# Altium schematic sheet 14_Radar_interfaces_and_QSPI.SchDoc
size 289 x 396 mm
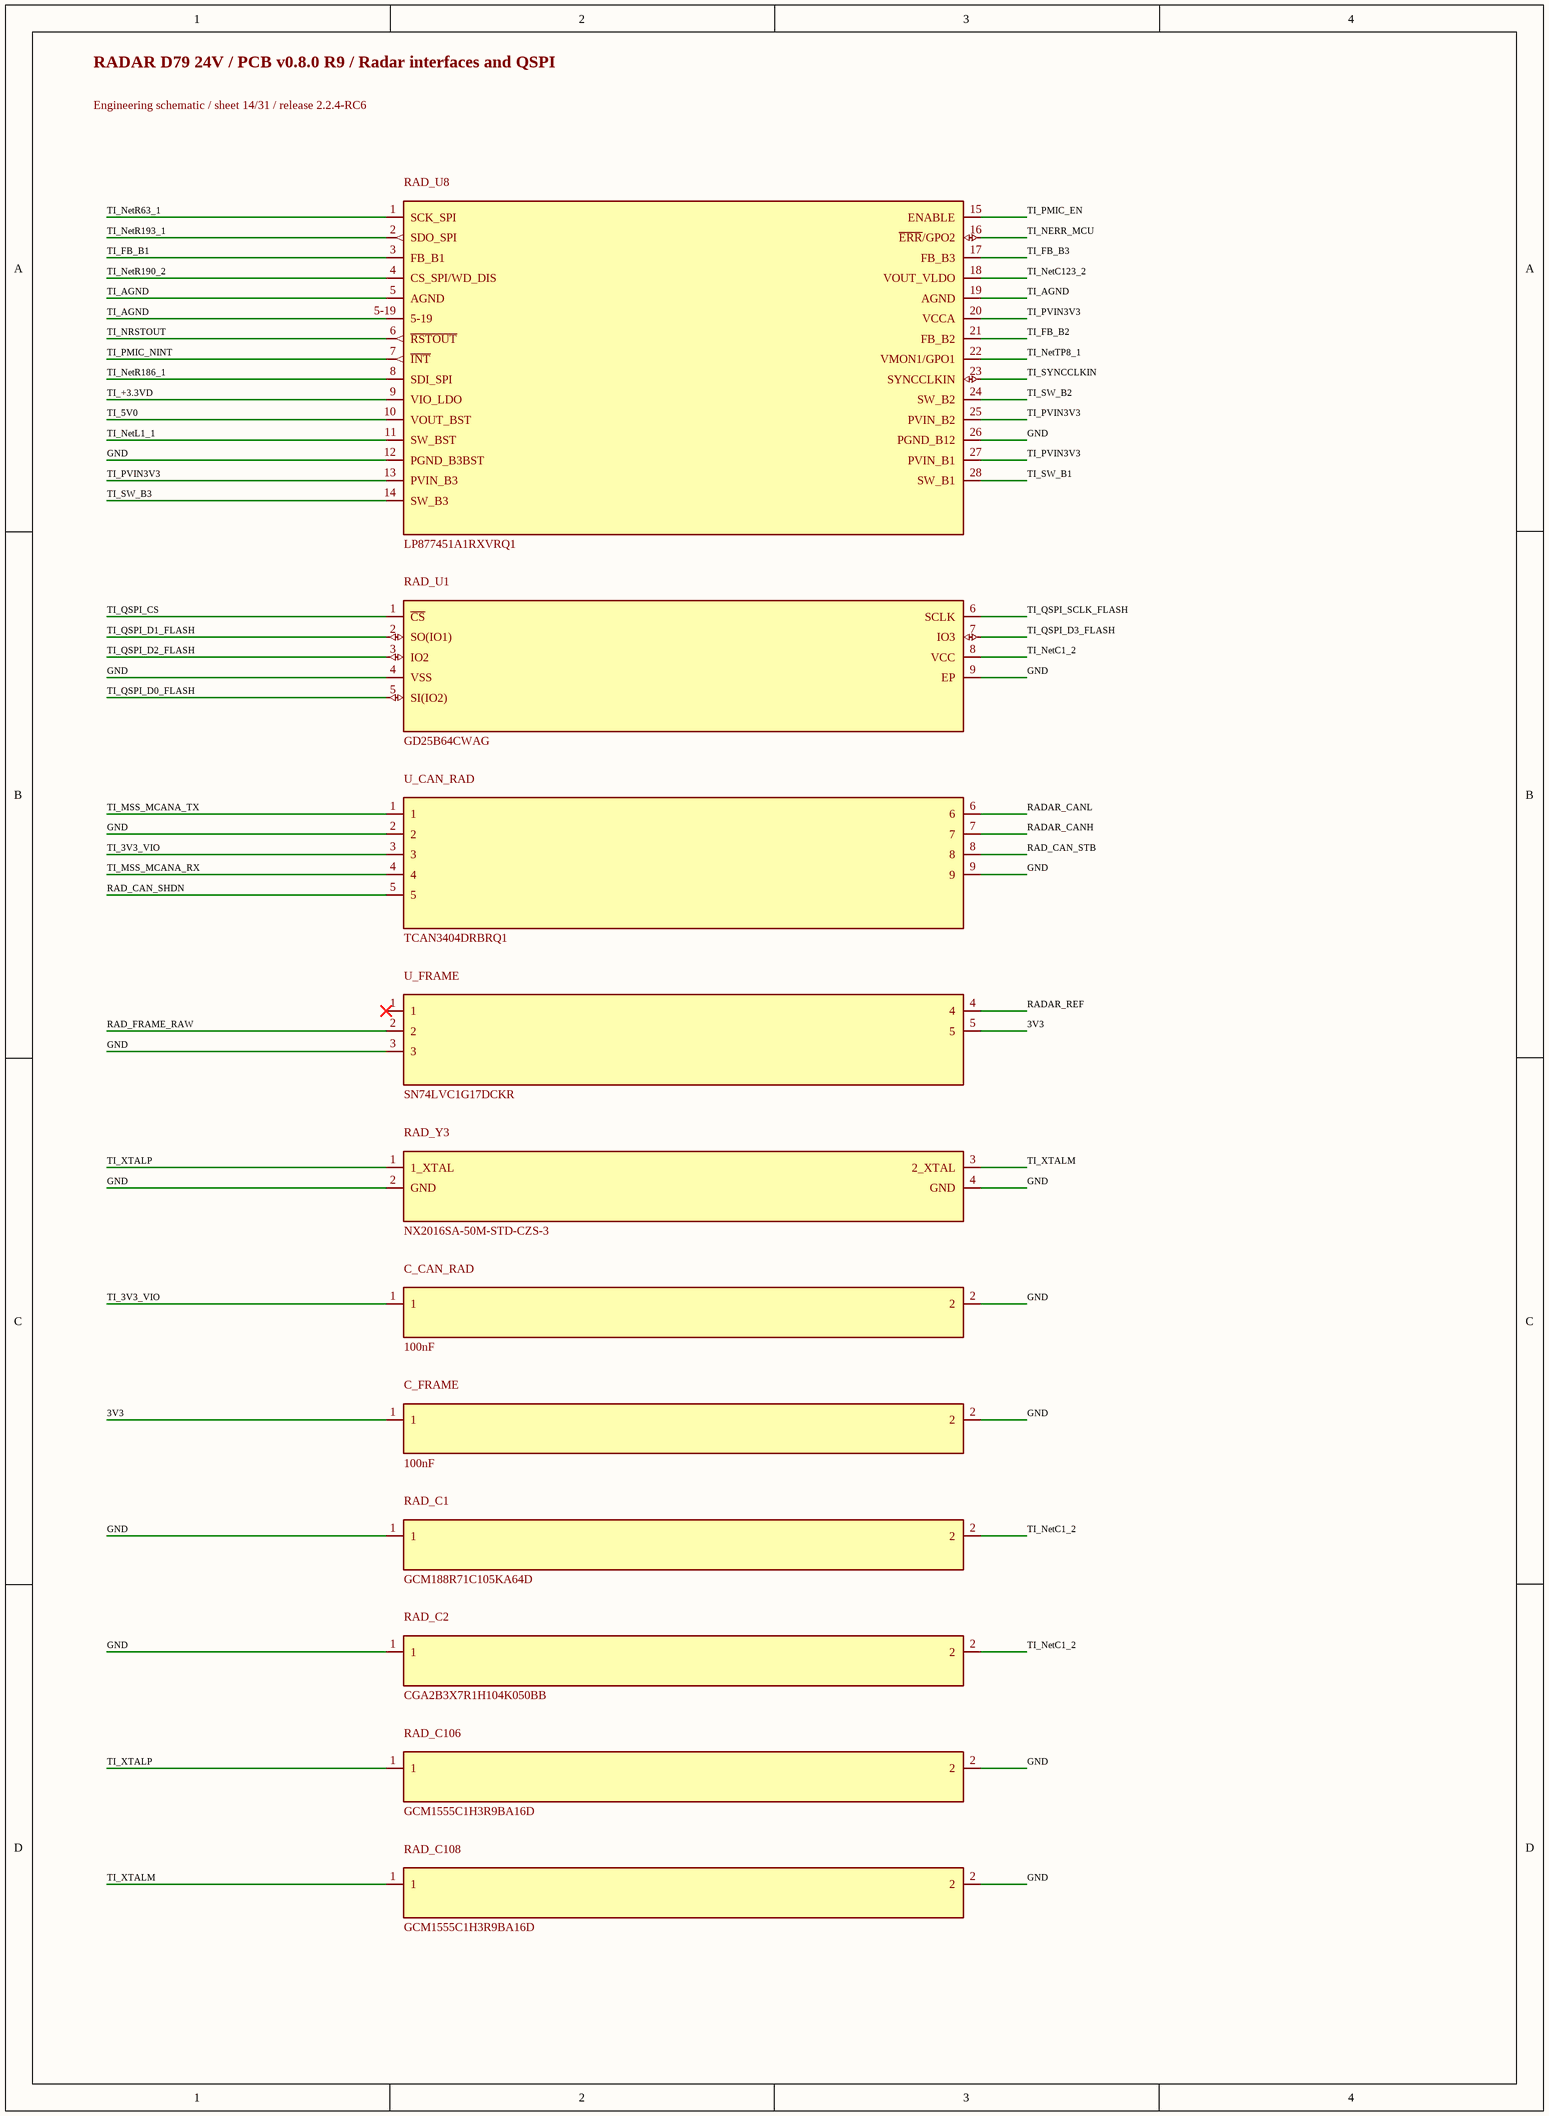
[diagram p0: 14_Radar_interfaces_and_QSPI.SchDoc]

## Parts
C_CAN_RAD  100nF  [C_0402_1005Metric]
C_FRAME  100nF  [C_0402_1005Metric]
RAD_C1  GCM188R71C105KA64D  [0603L]
RAD_C2  CGA2B3X7R1H104K050BB  [0402L]
RAD_C106  GCM1555C1H3R9BA16D  [FP-GCM1555C1H3R9BA16D_0402-MFG]
RAD_C108  GCM1555C1H3R9BA16D  [FP-GCM1555C1H3R9BA16D_0402-MFG]
RAD_U1  GD25B64CWAG  [FP-GD25B64CWAG_WSON8-IPC_C]
RAD_U8  LP877451A1RXVRQ1  [RXV0028A-MFG]
RAD_Y3  NX2016SA-50M-STD-CZS-3  [FP-NX2016SA-50M-STD-CZS-3_SMT4_2MM0_1MM6-MFG]
U_CAN_RAD  TCAN3404DRBRQ1  [Texas_DRB0008A]
U_FRAME  SN74LVC1G17DCKR  [DCK0005A_N]

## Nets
3V3: C_FRAME.1 U_FRAME.5
GND: C_CAN_RAD.2 C_FRAME.2 RAD_C1.1 RAD_C2.1 RAD_C106.2 RAD_C108.2 RAD_U1.4(VSS) RAD_U1.9(EP) RAD_U8.12(PGND_B3BST) RAD_U8.26(PGND_B12) RAD_Y3.2(GND) RAD_Y3.4(GND) U_CAN_RAD.2 U_CAN_RAD.9 U_FRAME.3
RAD_CAN_SHDN: U_CAN_RAD.5
RAD_CAN_STB: U_CAN_RAD.8
RAD_FRAME_RAW: U_FRAME.2
RADAR_CANH: U_CAN_RAD.7
RADAR_CANL: U_CAN_RAD.6
RADAR_REF: U_FRAME.4
TI_3V3_VIO: C_CAN_RAD.1 U_CAN_RAD.3
TI_5V0: RAD_U8.10(VOUT_BST)
TI_+3.3VD: RAD_U8.9(VIO_LDO)
TI_AGND: RAD_U8.5(AGND) RAD_U8.5-19 RAD_U8.19(AGND)
TI_FB_B1: RAD_U8.3(FB_B1)
TI_FB_B2: RAD_U8.21(FB_B2)
TI_FB_B3: RAD_U8.17(FB_B3)
TI_MSS_MCANA_RX: U_CAN_RAD.4
TI_MSS_MCANA_TX: U_CAN_RAD.1
TI_NERR_MCU: RAD_U8.16(~{ERR}/GPO2)
TI_NetC1_2: RAD_C1.2 RAD_C2.2 RAD_U1.8(VCC)
TI_NetC123_2: RAD_U8.18(VOUT_VLDO)
TI_NetL1_1: RAD_U8.11(SW_BST)
TI_NetR63_1: RAD_U8.1(SCK_SPI)
TI_NetR186_1: RAD_U8.8(SDI_SPI)
TI_NetR190_2: RAD_U8.4(CS_SPI/WD_DIS)
TI_NetR193_1: RAD_U8.2(SDO_SPI)
TI_NetTP8_1: RAD_U8.22(VMON1/GPO1)
TI_NRSTOUT: RAD_U8.6(~{RSTOUT})
TI_PMIC_EN: RAD_U8.15(ENABLE)
TI_PMIC_NINT: RAD_U8.7(~{INT})
TI_PVIN3V3: RAD_U8.13(PVIN_B3) RAD_U8.20(VCCA) RAD_U8.25(PVIN_B2) RAD_U8.27(PVIN_B1)
TI_QSPI_CS: RAD_U1.1(~{CS})
TI_QSPI_D0_FLASH: RAD_U1.5(SI(IO2))
TI_QSPI_D1_FLASH: RAD_U1.2(SO(IO1))
TI_QSPI_D2_FLASH: RAD_U1.3(IO2)
TI_QSPI_D3_FLASH: RAD_U1.7(IO3)
TI_QSPI_SCLK_FLASH: RAD_U1.6(SCLK)
TI_SW_B1: RAD_U8.28(SW_B1)
TI_SW_B2: RAD_U8.24(SW_B2)
TI_SW_B3: RAD_U8.14(SW_B3)
TI_SYNCCLKIN: RAD_U8.23(SYNCCLKIN)
TI_XTALM: RAD_C108.1 RAD_Y3.3(2_XTAL)
TI_XTALP: RAD_C106.1 RAD_Y3.1(1_XTAL)

Not connected (* = marked no-connect by the designer): U_FRAME 1*

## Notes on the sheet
- RADAR D79 24V / PCB v0.8.0 R9 / Radar interfaces and QSPI
- Engineering schematic / sheet 14/31 / release 2.2.4-RC6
